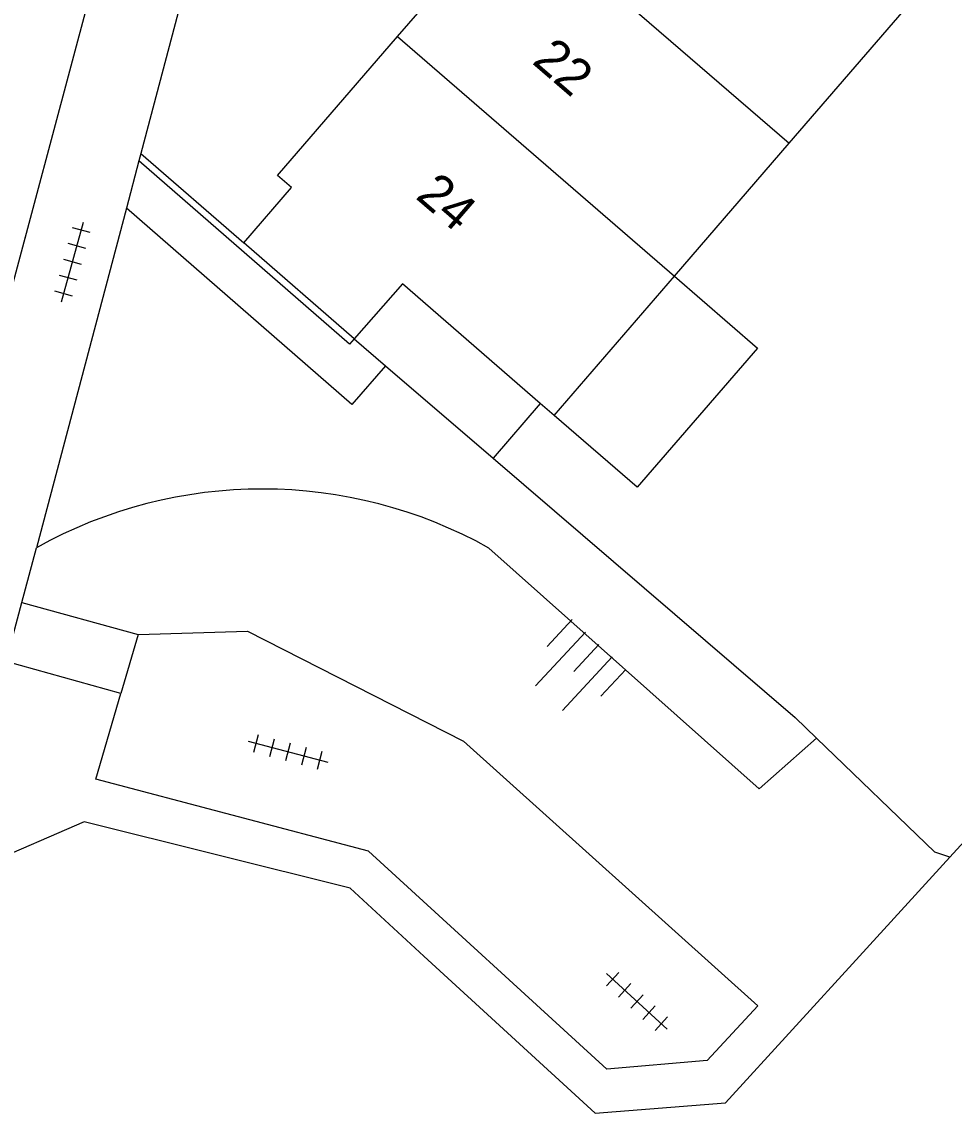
# Model space of a CAD drawing. Extents: x 128000 to 131008, y 398996 to 402500.
# Drawn here: x 128972.49 to 128997.94, y 399495.71 to 399525.51 of the extents above; entities that cross this region are included whole.
import ezdxf

# ---------------------------------------------------------------- set-up
doc = ezdxf.new("R2010")
doc.units = 0
for name, color, linetype in [('gg-afsc-erfafscheiding', 7, 'Continuous'), ('gg-anno-huisnummerreeks BGT', 7, 'Continuous'), ('gg-bbg-gedigitaliseerde bebouwing', 7, 'Continuous'), ('gg-bbg-hoofdgebouw', 7, 'Continuous'), ('gg-bbg-luifel en loopbrug', 7, 'Continuous'), ('gg-bbg-tussenscheiding', 7, 'Continuous'), ('gg-knt-BGT kruinlijn', 7, 'Continuous'), ('gg-knt-trap', 7, 'Continuous'), ('gg-knt-verharding', 7, 'Continuous'), ('gg-knt-verharding nz', 7, 'Continuous'), ('gg-kntw-beschoeiing', 7, 'Continuous'), ('gt-grn-vlakafsluiter', 7, 'Continuous'), ('gt-symb-talud symbool', 7, 'Continuous'), ('gt-symb-tegel verharding', 7, 'Continuous')]:
    doc.layers.add(name, color=color, linetype=linetype)

# ---------------------------------------------------------------- blocks, each defined once
blk = doc.blocks.new('gt0-TALUD_1')
at = {"layer": 'gt-symb-talud symbool'}
for p, q in [((-1, -1), (-1, 0)), ((-0.5, -2), (-0.5, 0)), ((0.5, -2), (0.5, 0)), ((1, -1), (1, 0)), ((0, -1), (0, 0))]:
    blk.add_line(p, q, dxfattribs=at)
blk = doc.blocks.new('gt0-TEG1')
at = {"layer": 'gt-symb-tegel verharding'}
for p, q in [((-1.125, 0), (1.125, 0)), ((-0.9, -0.25), (-0.9, 0.25)), ((-0.45, -0.25), (-0.45, 0.25)), ((0, -0.25), (0, 0.25)), ((0.45, -0.25), (0.45, 0.25)), ((0.9, -0.25), (0.9, 0.25))]:
    blk.add_line(p, q, dxfattribs=at)

msp = doc.modelspace()

# ---------------------------------------------------------------- linework, layer by layer
at = {"layer": 'gg-afsc-erfafscheiding'}
for p, q in [((128975.74, 399521.916), (128978.55, 399519.47)), ((128997.409, 399502.835), (128994.18, 399505.951))]:
    msp.add_line(p, q, dxfattribs=at)
msp.add_lwpolyline([(128985.352, 399513.594), (128993.598, 399506.512), (128994.18, 399505.951)], dxfattribs=at)
at = {"layer": 'gg-bbg-gedigitaliseerde bebouwing'}
for p, q in [((128993.439, 399522.191), (128996.577, 399525.823)), ((128990.304, 399518.561), (128993.439, 399522.191)), ((128987.02, 399514.76), (128990.304, 399518.561))]:
    msp.add_line(p, q, dxfattribs=at)
at = {"layer": 'gg-bbg-hoofdgebouw'}
for p, q in [((128982.745, 399525.102), (128985.875, 399528.726)), ((128981.56, 399516.85), (128978.55, 399519.47)), ((128987.02, 399514.76), (128986.642, 399515.088))]:
    msp.add_line(p, q, dxfattribs=at)
for points in [[(128978.55, 399519.47), (128979.85, 399520.98), (128979.47, 399521.31), (128982.745, 399525.102)], [(128986.642, 399515.088), (128982.88, 399518.35), (128981.56, 399516.85)]]:
    msp.add_lwpolyline(points, dxfattribs=at)
at = {"layer": 'gg-bbg-luifel en loopbrug'}
for p, q in [((128981.56, 399516.85), (128982.417, 399516.114)), ((128982.417, 399516.114), (128985.352, 399513.594)), ((128986.642, 399515.088), (128985.352, 399513.594))]:
    msp.add_line(p, q, dxfattribs=at)
msp.add_lwpolyline([(128990.304, 399518.561), (128992.574, 399516.6), (128989.291, 399512.799), (128987.02, 399514.76)], dxfattribs=at)
at = {"layer": 'gg-bbg-tussenscheiding'}
for p, q in [((128985.875, 399528.726), (128993.439, 399522.191)), ((128982.745, 399525.102), (128990.304, 399518.561))]:
    msp.add_line(p, q, dxfattribs=at)
at = {"layer": 'gg-knt-BGT kruinlijn'}
for q in [(128985.24, 399511.14), (128994.18, 399505.951)]:
    msp.add_line((128992.614, 399504.567), q, dxfattribs=at)
msp.add_arc((128979.055, 399500.071), 12.68, 60.8033, 119.104, dxfattribs=at)
at = {"layer": 'gg-knt-trap'}
for p, q in [((128972.063, 399508.044), (128972.49, 399509.65)), ((128972.49, 399509.65), (128975.66, 399508.78)), ((128975.66, 399508.78), (128975.19, 399507.17)), ((128975.19, 399507.17), (128972.063, 399508.044))]:
    msp.add_line(p, q, dxfattribs=at)
at = {"layer": 'gg-knt-verharding'}
for p, q in [((128974.698, 399527.551), (128970.826, 399513.079)), ((128976.84, 399526.07), (128975.74, 399521.916)), ((128975.74, 399521.916), (128975.686, 399521.711)), ((128975.343, 399520.419), (128972.887, 399511.15)), ((128972.49, 399509.65), (128972.887, 399511.15))]:
    msp.add_line(p, q, dxfattribs=at)
for points in [[(128981.56, 399516.85), (128981.435, 399516.707), (128975.686, 399521.711)], [(128982.417, 399516.114), (128981.5, 399515.06), (128975.343, 399520.419)], [(128975.66, 399508.78), (128978.65, 399508.87), (128984.55, 399505.87), (128992.58, 399498.64), (128991.2, 399497.15), (128988.46, 399496.91), (128981.95, 399502.86), (128974.51, 399504.83), (128975.19, 399507.17)]]:
    msp.add_lwpolyline(points, dxfattribs=at)
at = {"layer": 'gg-knt-verharding nz'}
msp.add_line((128975.686, 399521.711), (128975.343, 399520.419), dxfattribs=at)
at = {"layer": 'gg-kntw-beschoeiing'}
for p, q in [((128997.819, 399502.698), (129000, 399505.089)), ((128995.358, 399500), (128997.819, 399502.698))]:
    msp.add_line(p, q, dxfattribs=at)
for points in [[(128983.466, 399500), (128981.45, 399501.85), (128974.19, 399503.66), (128971.5, 399502.501), (128970.829, 399502.644)], [(128983.466, 399500), (128988.14, 399495.71), (128991.7, 399495.99), (128995.358, 399500)]]:
    msp.add_lwpolyline(points, dxfattribs=at)
at = {"layer": 'gt-grn-vlakafsluiter'}
msp.add_line((128997.819, 399502.698), (128997.409, 399502.835), dxfattribs=at)

# ---------------------------------------------------------------- block references
at = {"layer": 'gt-symb-talud symbool', "xscale": 0.9998444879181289, "yscale": 0.9998444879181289, "rotation": -42.85190842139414}
msp.add_blockref('gt0-TALUD_1', (128988.241, 399508.506), dxfattribs=at)
at = {"layer": 'gt-symb-tegel verharding'}
for p, rotation in [((128973.874, 399518.951), 74.5740296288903), ((128979.757, 399505.578), -14.828108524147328), ((128989.279, 399498.76), -42.447101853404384)]:
    msp.add_blockref('gt0-TEG1', p, dxfattribs=dict(at, rotation=rotation))

# ---------------------------------------------------------------- texts
at = {"layer": 'gg-anno-huisnummerreeks BGT'}
for s, p in [('22', (128986.389, 399524.391)), ('24', (128983.208, 399520.707))]:
    msp.add_text(s, height=1, rotation=319.2, dxfattribs=at).set_placement(p)

doc.saveas('drawing.dxf')
